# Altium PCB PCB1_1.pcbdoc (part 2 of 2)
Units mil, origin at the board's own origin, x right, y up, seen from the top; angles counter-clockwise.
Board outline 2585 x 2710 mil, 2 copper layers (Top Layer, Bottom Layer); 39 components, 30 nets, 170 pads, 81 vias.
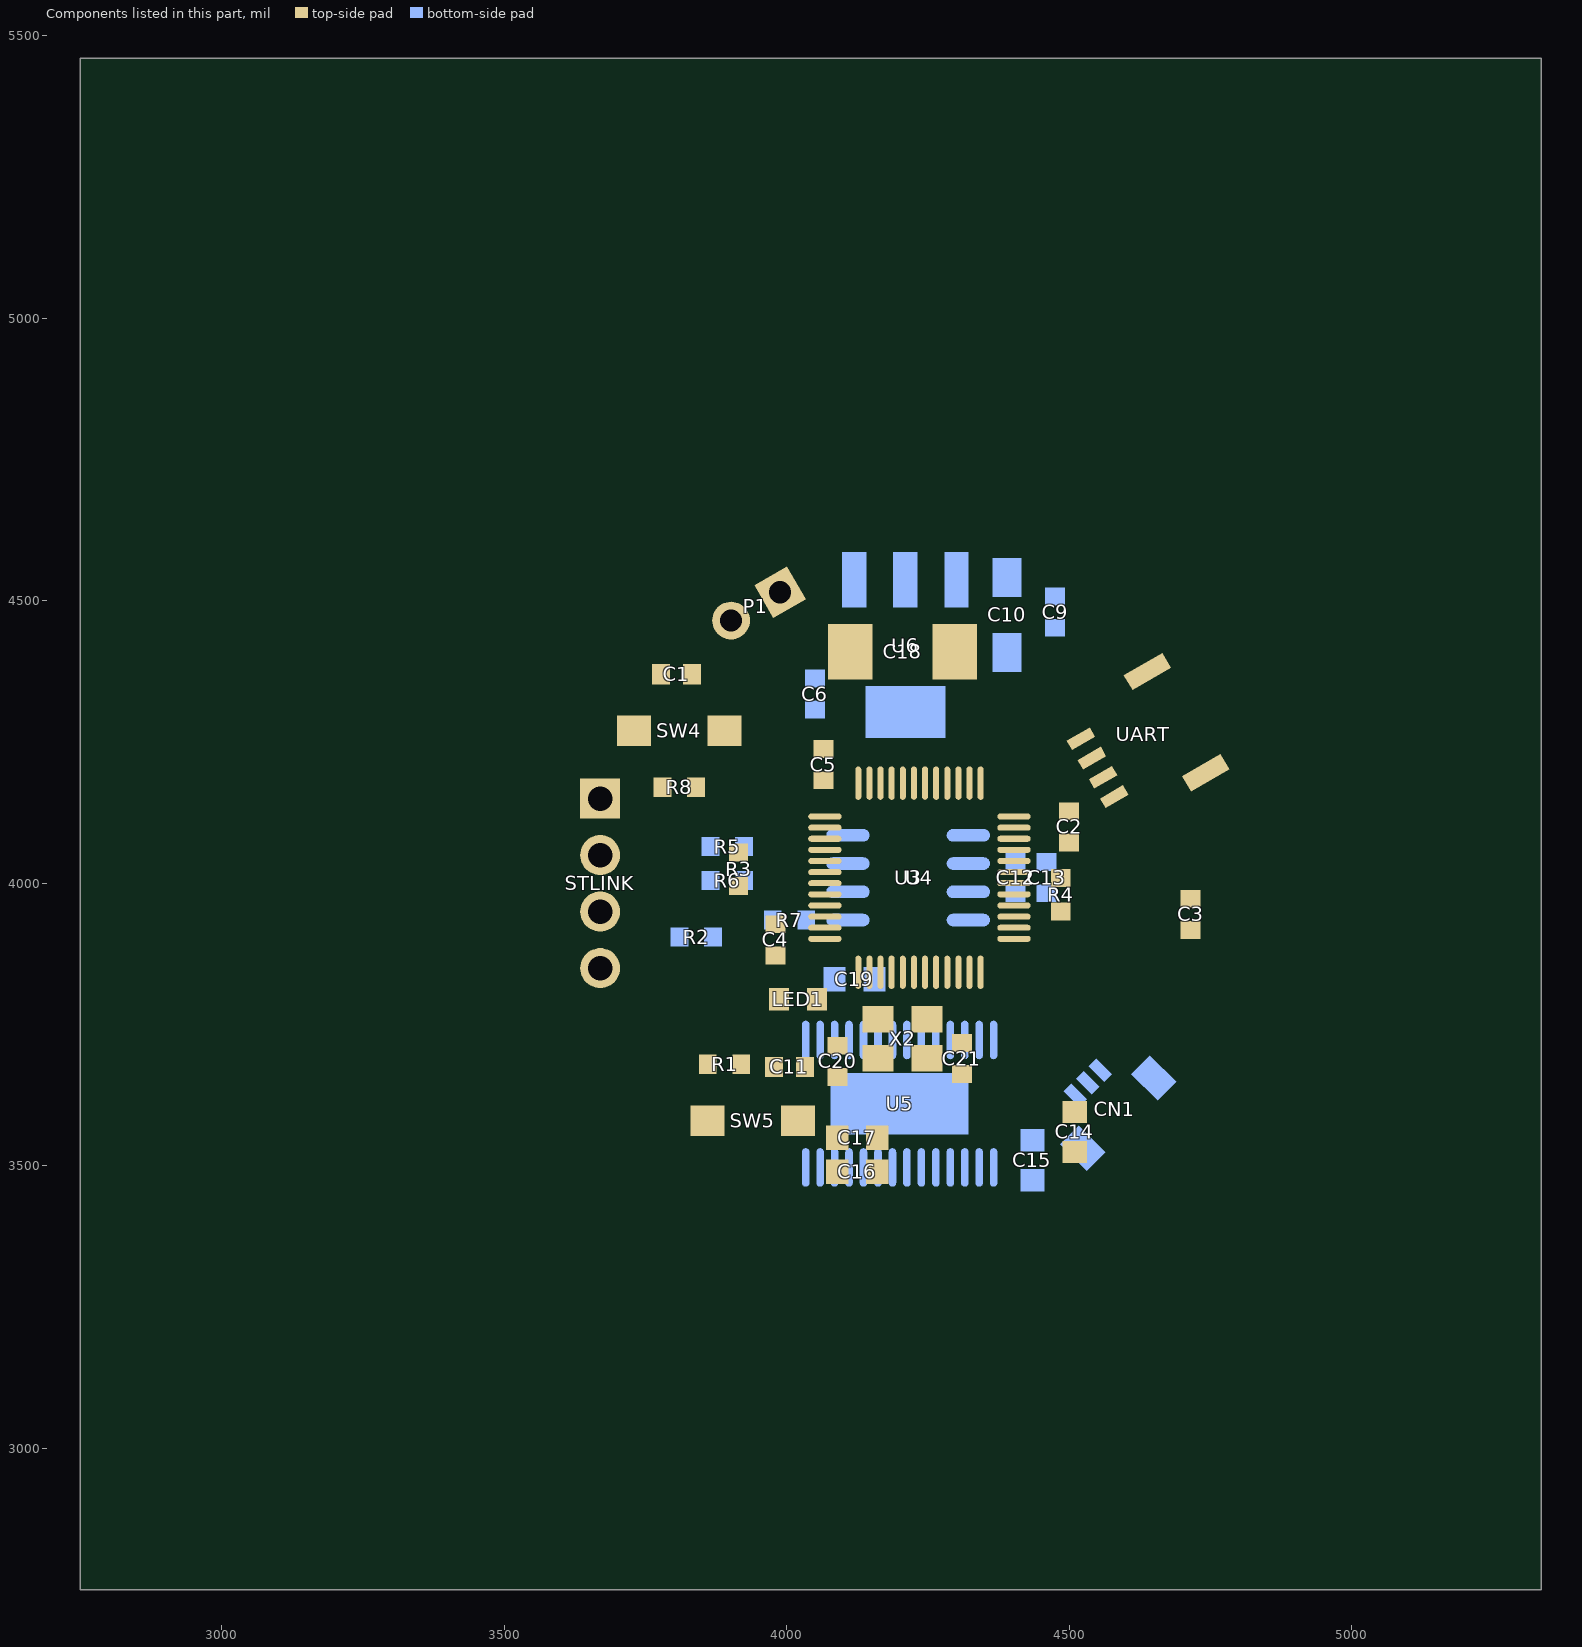
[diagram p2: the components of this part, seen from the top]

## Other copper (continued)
Bottom Layer:
  region net VCC3V3: 4535,4090 4555,4080 ccw(c4486.83,4080) 4552,4100 4538,4102.86 ccw(c4564.06,4090)
  region net $1N8596: 4074.57,3752.8 4074.51,3750.93 4074.32,3749.07 4074.01,3747.24 4073.57,3745.46 4073.02,3743.73 4072.34,3742.08 4071.55,3740.51 4070.64,3739.05 4069.6,3737.7 4069.05,3737.08 4068.46,3736.49 4067.84,3735.94 4067.2,3735.42 4066.52,3734.95 4065.82,3734.52 4065.09,3734.13 4064.33,3733.79 4063.55,3733.49 4062.73,3733.25 4061.89,3733.06 4061.02,3732.91 4060.12,3732.83 4059.2,3732.8 4059.2,3712.8 4074.57,3722.8 4094.57,3752.8
  region net VCC: 4284.6,3510.02 4294.6,3510.02 4289.6,3520.02 4282.53,3544.54
  region net EN: 4217.8,3699.27 4207.8,3699.21 ccw(c4229.16,3699.21) 4209.3,3691.34 4216.3,3690.77 ccw(c4192.97,3699.27)
  region net EN: 4278.14,3678.93 4277.29,3679.86 4276.44,3680.92 4275.6,3682.11 4274.39,3684.07 4273.24,3686.22 4272.18,3688.48 4271.24,3690.81 4270.43,3693.16 4269.79,3695.47 4269.32,3697.68 4269.12,3699.07 4269.01,3700.38 4269,3701 4259,3701 4258.95,3699.74 4258.79,3698.38 4258.55,3696.95 4258.02,3694.71 4257.31,3692.38 4256.46,3690.03 4255.47,3687.72 4254.39,3685.49 4253.21,3683.4 4251.98,3681.5 4251.14,3680.38 4250.29,3679.38 4249.86,3678.93 4256.93,3671.86 4257.63,3672.48 4258.41,3673.02 4259.24,3673.47 4260.13,3673.85 4261.06,3674.14 4262.03,3674.34 4263.01,3674.47 4264,3674.51 4264.99,3674.47 4265.97,3674.34 4266.94,3674.14 4267.87,3673.85 4268.76,3673.47 4269.59,3673.02 4270.37,3672.48 4271.07,3671.86
  region net RESET: 3893.54,3908.54 3886.46,3901.46 cw(c3873.59,3888.59) 3890.92,3894.18 3904.9,3900 cw(c3929.24,3944.24)
  region net VCC3V3: 3759.14,3915 3758.46,3915.02 3757.05,3915.16 3756.36,3915.29 3755.68,3915.45 3755.04,3915.64 3754.45,3915.87 3753.92,3916.12 3753.45,3916.4 3753.08,3916.72 3752.8,3917.06 3752.62,3917.42 3752.58,3917.82 3752.66,3918.24 3752.89,3918.68 3753.28,3919.14 3710.86,3876.72 3712.43,3878.19 3714.14,3879.62 3716.64,3881.45 3719.34,3883.21 3722.98,3885.26 3726.84,3887.16 3730.87,3888.89 3735.86,3890.71 3740.91,3892.25 3745.93,3893.46 3750.03,3894.22 3753.97,3894.73 3756.98,3894.95 3759.14,3895
  region net RESET: 4006.64,3875.78 4005.26,3874.51 4003.79,3873.36 4002.24,3872.32 4000.62,3871.42 3998.95,3870.65 3997.24,3870.02 3995.5,3869.55 3993.75,3869.23 3992,3869.08 3991.13,3869.07 3990.26,3869.1 3989.4,3869.18 3988.55,3869.31 3987.71,3869.48 3986.88,3869.7 3986.06,3869.97 3985.26,3870.28 3984.47,3870.65 3983.71,3871.07 3982.96,3871.54 3982.24,3872.07 3981.53,3872.65 3980.86,3873.28 3966.72,3859.14 3968.43,3857.34 3970.55,3854.85 3972.62,3852.13 3975.01,3848.62 3977.24,3844.88 3979.29,3840.99 3980.81,3837.67 3982.13,3834.31 3983.24,3830.95 3983.95,3828.29 3984.48,3825.67 3984.77,3823.74 3984.94,3821.84 3985,3820 4005,3820 4005.08,3822.5 4005.3,3825.13 4005.79,3828.56 4006.48,3832.11 4007.58,3836.45 4008.95,3840.8 4010.57,3845.08 4012.09,3848.54 4013.76,3851.83 4015.19,3854.32 4016.7,3856.66 4018.28,3858.81 4019.52,3860.29 4020.78,3861.64
  region net SDA: 3950,4015 3945.86,3995 ccw(c3945.86,4044.67) 3962.86,3998 3962.86,4012 ccw(c3950,3985.94)
  region net SCL: 3990,4025 3994.14,4045 ccw(c3994.14,3995.33) 3977.14,4042 3977.14,4028 ccw(c3990,4054.06)
  region net VCC: 4380.86,4513.11 4382.23,4514.39 4383.75,4515.67 4386.01,4517.36 4389.13,4519.42 4392.54,4521.4 4396.92,4523.63 4401.51,4525.68 4406.2,4527.48 4410.87,4528.99 4414.69,4530 4418.35,4530.76 4421.14,4531.16 4423.12,4531.33 4425,4531.39 4360.86,4531.39 4361.54,4531.37 4362.95,4531.23 4363.64,4531.1 4364.32,4530.94 4364.96,4530.75 4365.55,4530.52 4366.08,4530.27 4366.55,4529.99 4366.92,4529.67 4367.2,4529.33 4367.38,4528.97 4367.42,4528.57 4367.34,4528.15 4367.11,4527.71 4366.72,4527.25
  region net VCC3V3: 4306.72,4244.14 4308,4242.77 4309.28,4241.25 4310.97,4238.99 4313.03,4235.87 4315.01,4232.46 4317.24,4228.08 4319.29,4223.49 4321.09,4218.8 4322.6,4214.13 4323.61,4210.31 4324.37,4206.65 4324.77,4203.86 4324.94,4201.88 4325,4200 4345,4200 4335,4220 4320.86,4258.28
  region net VCC: 4115,3461.34 4105,3461.34 4104.98,3460.77 4104.91,3460.2 4104.8,3459.63 4104.66,3459.07 4104.48,3458.51 4104.02,3457.4 4103.46,3456.32 4102.81,3455.28 4102.11,3454.3 4101,3452.94 4119,3452.94 4117.89,3454.3 4117.19,3455.28 4116.54,3456.32 4115.98,3457.4 4115.52,3458.51 4115.34,3459.07 4115.2,3459.63 4115.09,3460.2 4115.02,3460.77
  region net V: 4206.98,3450.09 4199.91,3443.02 4200.3,3442.6 4200.65,3442.15 4200.98,3441.67 4201.27,3441.17 4201.54,3440.64 4202,3439.54 4202.37,3438.38 4202.65,3437.19 4202.85,3436 4203.02,3434.25 4215.75,3446.98 4214,3447.15 4212.81,3447.35 4211.62,3447.63 4210.46,3448 4209.36,3448.46 4208.83,3448.73 4208.33,3449.02 4207.85,3449.35 4207.4,3449.7
  region net W: 4171.98,3450.09 4164.91,3443.02 4165.3,3442.6 4165.65,3442.15 4165.98,3441.67 4166.27,3441.17 4166.54,3440.64 4167,3439.54 4167.37,3438.38 4167.65,3437.19 4167.85,3436 4168.02,3434.25 4180.75,3446.98 4179,3447.15 4177.81,3447.35 4176.62,3447.63 4175.46,3448 4174.36,3448.46 4173.83,3448.73 4173.33,3449.02 4172.85,3449.35 4172.4,3449.7
  region net $1N8586: 4369.84,3472.24 4362.76,3465.16 4363.08,3464.67 4363.24,3464 4363.29,3463.22 4363.26,3462.37 4363.03,3459.89 4363.02,3459.25 4375.75,3471.98 4375.11,3471.97 4372.63,3471.74 4371.78,3471.71 4371,3471.76 4370.33,3471.92
  region net $1N8587: 4345.7,3471.34 4335.7,3471.34 4335.77,3470.42 4336.39,3466.93 4336.54,3465.74 4336.56,3464.63 4336.4,3463.68 4336,3462.94 4354,3462.94 4353.56,3463.38 4352.46,3464.32 4349.07,3466.84 4347.78,3467.92 4347.21,3468.47 4346.71,3469.03 4346.29,3469.6 4345.97,3470.17 4345.77,3470.75
  region net $1N8589: 4323.02,3434.91 4330.09,3441.98 4329.7,3442.4 4329.35,3442.85 4329.02,3443.33 4328.73,3443.83 4328.46,3444.36 4328,3445.46 4327.63,3446.62 4327.35,3447.81 4327.15,3449 4326.98,3450.75 4314.25,3438.02 4316,3437.85 4317.19,3437.65 4318.38,3437.37 4319.54,3437 4320.64,3436.54 4321.17,3436.27 4321.67,3435.98 4322.15,3435.65 4322.6,3435.3
  region net $1N8589: 4320.2,3466.34 4310.2,3466.34 4310.18,3465.75 4310.11,3465.16 4309.99,3464.59 4309.84,3464.02 4309.65,3463.46 4309.42,3462.91 4308.89,3461.84 4308.25,3460.8 4307.54,3459.81 4306.39,3458.39 4306,3457.94 4324,3457.94 4323.29,3458.8 4322.6,3459.75 4321.96,3460.78 4321.39,3461.87 4320.9,3462.99 4320.53,3464.12 4320.39,3464.68 4320.29,3465.24 4320.22,3465.79
  region net U: 4269,3456.34 4259,3456.34 4259.04,3455.83 4259.16,3455.29 4259.34,3454.74 4259.82,3453.61 4260.92,3451.32 4261.14,3450.77 4261.32,3450.23 4261.43,3449.72 4261.47,3449.23 4261.42,3448.76 4261.27,3448.33 4261,3447.94 4279,3447.94 4278.48,3448.46 4277.85,3448.96 4276.38,3449.91 4273.06,3451.78 4271.5,3452.77 4270.82,3453.29 4270.21,3453.83 4269.71,3454.4 4269.33,3455.01 4269.08,3455.65
  region net EN: 4248.02,3934.91 4255.09,3941.98 4254.7,3942.4 4254.35,3942.85 4254.02,3943.33 4253.73,3943.83 4253.46,3944.36 4253,3945.46 4252.63,3946.62 4252.35,3947.81 4252.15,3949 4251.98,3950.75 4239.25,3938.02 4241,3937.85 4242.19,3937.65 4243.38,3937.37 4244.54,3937 4245.64,3936.54 4246.17,3936.27 4246.67,3935.98 4247.15,3935.65 4247.6,3935.3
  region net RESET: 3894.48,3907.59 3887.41,3900.52 3887.75,3900.09 3888.01,3899.57 3888.2,3898.97 3888.33,3898.31 3888.41,3897.58 3888.44,3896.02 3888.28,3893.53 3888.03,3890.47 3888.01,3889.82 3888.02,3889.25 3900.75,3901.98 3900.06,3902.05 3899.47,3902.17 3898.95,3902.35 3898.51,3902.57 3898.12,3902.83 3897.78,3903.13 3897.47,3903.46 3897.19,3903.83 3896.38,3905.1 3895.76,3906.06 3895.39,3906.56 3894.97,3907.07
  region net PWM1: 4357.41,3779.48 4364.48,3772.41 4364.97,3772.93 4365.39,3773.44 4366.08,3774.43 4366.92,3775.77 4367.19,3776.17 4367.47,3776.54 4367.78,3776.87 4368.12,3777.17 4368.51,3777.43 4368.95,3777.65 4369.47,3777.83 4370.06,3777.95 4370.75,3778.02 4358.02,3790.75 4358.01,3790.18 4358.07,3788.83 4358.41,3784.81 4358.44,3783.18 4358.41,3782.42 4358.33,3781.69 4358.2,3781.03 4358.01,3780.43 4357.75,3779.91
  region net PWM2: 4314.15,3786.22 4321.22,3779.15 4321.76,3779.57 4322.39,3779.86 4323.09,3780.01 4323.85,3780.06 4324.66,3780.02 4325.51,3779.9 4327.31,3779.5 4330.98,3778.47 4332.69,3778.11 4333.49,3778.02 4334.22,3778.02 4321.5,3790.75 4321.21,3789.87 4320.54,3789.18 4319.59,3788.64 4317.26,3787.78 4316.07,3787.35 4315,3786.84
  region net PWM3: 4278.66,3800 4278.66,3790 4279.23,3789.98 4279.8,3789.91 4280.37,3789.8 4280.93,3789.66 4281.49,3789.48 4282.6,3789.02 4283.68,3788.46 4284.72,3787.81 4285.7,3787.11 4287.06,3786 4287.06,3804 4285.7,3802.89 4284.72,3802.19 4283.68,3801.54 4282.6,3800.98 4281.49,3800.52 4280.93,3800.34 4280.37,3800.2 4279.8,3800.09 4279.23,3800.02
  region net $1N18711: 4080.54,3925 4080.54,3945 cw(c4080.54,4012.72) 4050.54,3952.01 4050.54,3917.99 cw(c4080.54,3857.28)
  region net $1N8589: 4402.74,3459.81 4402.74,3445.67 cw(c4425.24,3423.17) 4422.55,3454.88 4413.35,3481.02 cw(c4376.22,3486.33)
  region net VCC: 4398.35,3549.87 4398.35,3539.87 cw(c4398.35,3521.12) 4413.35,3532.37 4413.35,3557.37 cw(c4398.35,3568.62)
  region net VCC3V3: 4090,4297.44 4090,4317.44 cw(c4090,4436.2) 4067.72,4319.55 4067.72,4295.33 cw(c4090,4178.69)
  region net VCC3V3: 4011.07,4280.21 4029.62,4270.48 cw(c4085.93,4214.17) 4067.72,4291.69 4032.28,4322.64 cw(c3958.04,4333.25)
  region net $1N8596: 4059.2,3712.8 4059.2,3732.8 4057.44,3732.87 4055.7,3733.06 4053.99,3733.38 4052.32,3733.83 4050.7,3734.39 4049.15,3735.07 4047.68,3735.87 4046.31,3736.78 4045.05,3737.81 4044.46,3738.36 4043.91,3738.93 4043.39,3739.54 4042.91,3740.17 4042.47,3740.82 4042.06,3741.5 4041.7,3742.21 4041.38,3742.93 4041.1,3743.69 4040.87,3744.46 4040.69,3745.26 4040.56,3746.09 4040.48,3746.93 4040.45,3747.8 4040.45,3697.8 4040.48,3698.67 4040.56,3699.51 4040.69,3700.34 4040.87,3701.14 4041.1,3701.91 4041.38,3702.67 4041.7,3703.39 4042.06,3704.1 4042.47,3704.78 4042.91,3705.43 4043.39,3706.06 4043.91,3706.67 4044.46,3707.24 4045.05,3707.79 4046.31,3708.82 4047.68,3709.73 4049.15,3710.53 4050.7,3711.21 4052.32,3711.77 4053.99,3712.22 4055.7,3712.54 4057.44,3712.73
  region net $1N8596: 4084.8,3712.8 4084.8,3732.8 4083.04,3732.86 4081.28,3733.06 4079.56,3733.38 4077.88,3733.82 4076.25,3734.38 4074.69,3735.06 4073.22,3735.86 4071.84,3736.77 4070.57,3737.78 4069.98,3738.34 4069.43,3738.91 4068.91,3739.52 4068.42,3740.14 4067.98,3740.8 4067.57,3741.48 4067.2,3742.19 4066.88,3742.92 4066.6,3743.67 4066.37,3744.45 4066.19,3745.25 4066.06,3746.08 4065.98,3746.93 4065.95,3747.8 4065.95,3697.8 4065.98,3698.67 4066.06,3699.52 4066.19,3700.35 4066.37,3701.15 4066.6,3701.93 4066.88,3702.68 4067.2,3703.41 4067.57,3704.12 4067.98,3704.8 4068.42,3705.46 4068.91,3706.08 4069.43,3706.69 4069.98,3707.26 4070.57,3707.82 4071.84,3708.83 4073.22,3709.74 4074.69,3710.54 4076.25,3711.22 4077.88,3711.78 4079.56,3712.22 4081.28,3712.54 4083.04,3712.74
  region net $1N8596: 4033.7,3732.8 4033.7,3712.8 4035.46,3712.73 4037.2,3712.54 4038.91,3712.22 4040.58,3711.77 4042.2,3711.21 4043.75,3710.53 4045.22,3709.73 4046.59,3708.82 4047.85,3707.79 4048.44,3707.24 4048.99,3706.67 4049.51,3706.06 4049.99,3705.43 4050.43,3704.78 4050.84,3704.1 4051.2,3703.39 4051.52,3702.67 4051.8,3701.91 4052.03,3701.14 4052.21,3700.34 4052.34,3699.51 4052.42,3698.67 4052.45,3697.8 4052.45,3747.8 4052.42,3746.93 4052.34,3746.09 4052.21,3745.26 4052.03,3744.46 4051.8,3743.69 4051.52,3742.93 4051.2,3742.21 4050.84,3741.5 4050.43,3740.82 4049.99,3740.17 4049.51,3739.54 4048.99,3738.93 4048.44,3738.36 4047.85,3737.81 4046.59,3736.78 4045.22,3735.87 4043.75,3735.07 4042.2,3734.39 4040.58,3733.83 4038.91,3733.38 4037.2,3733.06 4035.46,3732.87
  region net $1N8596: 4059.2,3732.8 4059.2,3712.8 4060.96,3712.74 4062.72,3712.54 4064.44,3712.22 4066.12,3711.78 4067.75,3711.22 4069.31,3710.54 4070.78,3709.74 4072.16,3708.83 4073.43,3707.82 4074.02,3707.26 4074.57,3706.69 4075.09,3706.08 4075.58,3705.46 4076.02,3704.8 4076.43,3704.12 4076.8,3703.41 4077.12,3702.68 4077.4,3701.93 4077.63,3701.15 4077.81,3700.35 4077.94,3699.52 4078.02,3698.67 4078.05,3697.8 4078.05,3747.8 4078.02,3746.93 4077.94,3746.08 4077.81,3745.25 4077.63,3744.45 4077.4,3743.67 4077.12,3742.92 4076.8,3742.19 4076.43,3741.48 4076.02,3740.8 4075.58,3740.14 4075.09,3739.52 4074.57,3738.91 4074.02,3738.34 4073.43,3737.78 4072.16,3736.77 4070.78,3735.86 4069.31,3735.06 4067.75,3734.38 4066.12,3733.82 4064.44,3733.38 4062.72,3733.06 4060.96,3732.86
  region net EN: 4217.8,3769.68 4207.8,3769.68 4207.85,3767.77 4208.08,3764.97 4208.44,3761.59 4208.5,3760.22 4208.48,3759.31 4208.4,3758.39 4208.25,3757.43 4208.03,3756.44 4207.71,3755.41 4207.28,3754.31 4206.75,3753.13 4218.85,3753.13 4218.32,3754.31 4217.89,3755.41 4217.57,3756.44 4217.35,3757.43 4217.2,3758.39 4217.12,3759.31 4217.1,3760.22 4217.16,3761.59 4217.62,3766.04 4217.78,3768.38
  region net EN: 4207.8,3687.8 4217.8,3687.8 4217.88,3688.37 4219.28,3693.97 4219.47,3694.88 4219.55,3695.45 4206.05,3695.45 4206.32,3694.82 4207.53,3689.56
  region net PWM3: 4245,3766.57 4235,3770.98 4234.86,3769.84 4231.69,3750.54 4231.65,3750.15 4245.15,3750.15
  region net EN: 4259,3686 4269,3686 4269.03,3687.65 4269.17,3689.32 4269.3,3690.14 4269.49,3690.94 4269.73,3691.72 4270.05,3692.47 4257.95,3692.47 4258.27,3691.72 4258.51,3690.94 4258.7,3690.14 4258.83,3689.32 4258.97,3687.65
  region net VCC: 4105,3450.8 4115,3449.91 4116.47,3463.37 4117.15,3469.85 4103.65,3469.85 4104.57,3457.53
  region net W: 4156.6,3453.4 4166.6,3453.4 4168.27,3468.9 4168.35,3469.85 4154.85,3469.85 4156.52,3454.35
  region net V: 4182.2,3462.8 4192.2,3462.8 4192.28,3463.35 4193.4,3467.44 4193.87,3469.3 4193.95,3469.85 4180.45,3469.85 4180.72,3469.31 4181.93,3464.46
  region net U: 4259,3450.32 4269,3450.32 4270.67,3468.76 4270.75,3469.85 4257.25,3469.85 4258.92,3451.4
  region net VCC: 4306.96,3534.89 4299.82,3541.9 4298.63,3540.78 4297.44,3539.79 4296.27,3538.93 4294.72,3537.94 4292.85,3536.9 4289.08,3535.03 4287.86,3534.37 4287.01,3533.85 4286.48,3533.47 4285.98,3533.08 4285.51,3532.65 4285.08,3532.18 4284.68,3531.68 4284.31,3531.13 4283.98,3530.53 4283.69,3529.88 4283.44,3529.17 4283.23,3528.39 4283.07,3527.55 4282.95,3526.63 4282.87,3525.63 4282.85,3524.55 4296.35,3524.55 4296.44,3525.25 4296.7,3525.96 4297.1,3526.67 4297.63,3527.37 4298.28,3528.07 4299.01,3528.77 4300.66,3530.13 4304.99,3533.27 4306.4,3534.37
  region net $1N8589: 4310.2,3450.32 4320.2,3450.32 4321.87,3468.76 4321.95,3469.85 4308.45,3469.85 4308.72,3467.36
  region net $1N8587: 4335.7,3459.3 4345.7,3459.3 4345.78,3460 4347.37,3469.15 4347.45,3469.85 4333.95,3469.85 4334.03,3469.72 4335.15,3463.34 4335.62,3460.08
  region net $1N8586: 4371.46,3456.46 4378.54,3463.54 4378.02,3464.02 4377.51,3464.44 4376.52,3465.13 4375.17,3465.99 4374.76,3466.27 4374.4,3466.56 4374.06,3466.87 4373.77,3467.22 4373.52,3467.61 4373.32,3468.06 4373.17,3468.58 4373.08,3469.17 4373.05,3469.85 4359.55,3469.85 4359.94,3470.61 4360.99,3469.95 4362.53,3468.25 4368.35,3460.4 4370.1,3458.07
  region net VCC3V3: 3855.34,4017.99 3875.34,4017.99 cw(c4089.73,4017.99) 3877.45,4047.99 3853.23,4047.99 cw(c3640.95,4017.99)
  region net $1N8596: 4074.57,3778.35 4094.57,3778.35 cw(c4308.96,3778.35) 4096.68,3808.35 4072.46,3808.35 cw(c3860.18,3778.35)
  region net $1N18711: 4046.28,3945 4046.28,3925 4046.96,3925.03 4047.68,3925.11 4049.24,3925.42 4050.92,3925.89 4055.5,3927.52 4062.14,3929.94 4063.94,3930.45 4065.64,3930.83 4066.45,3930.94 4067.22,3931.01 4067.96,3931.02 4068.65,3930.98 4069.3,3930.86 4069.91,3930.68 4070.46,3930.42 4070.95,3930.08 4071.39,3929.65 4071.77,3929.14 4071.77,3940.86 4071.39,3940.35 4070.95,3939.92 4070.46,3939.58 4069.91,3939.32 4069.3,3939.14 4068.65,3939.02 4067.96,3938.98 4067.22,3938.99 4066.45,3939.06 4064.8,3939.34 4063.05,3939.79 4060.28,3940.69 4052.7,3943.51 4050.06,3944.36 4048.44,3944.76 4047.68,3944.89 4046.96,3944.97
  region net SDA: 4046.28,3995 4046.28,3975 4081.3,3973.81 4081.3,3996.19
  region net SCL: 4046.28,4045 4046.28,4025 4081.3,4023.81 4081.3,4046.19
  region net VCC3V3: 4383.72,4025 4383.72,4045 4348.7,4046.19 4348.7,4023.81
  region net VCC3V3: 4331.5,4076.19 4311.5,4076.19 4311.34,4066.5 4311.04,4062.58 4310.71,4060.11 4310.37,4058.33 4309.95,4056.64 4309.44,4055.04 4309.05,4054.03 4308.6,4053.07 4308.11,4052.16 4307.56,4051.3 4306.95,4050.5 4306.29,4049.76 4305.56,4049.08 4304.77,4048.47 4303.91,4047.92 4302.98,4047.44 4301.98,4047.04 4300.9,4046.71 4299.75,4046.46 4298.51,4046.29 4297.19,4046.2 4296.5,4046.19 4346.5,4046.19 4345.14,4046.23 4343.86,4046.36 4342.66,4046.57 4341.55,4046.86 4340.51,4047.23 4339.55,4047.67 4338.65,4048.19 4337.83,4048.77 4337.07,4049.41 4336.37,4050.13 4335.74,4050.9 4335.16,4051.73 4334.64,4052.61 4334.17,4053.55 4333.75,4054.53 4333.38,4055.56 4332.9,4057.19 4332.51,4058.91 4332.11,4061.33 4331.78,4064.52 4331.54,4069.9
  region net VCC3V3: 4311.5,4043.81 4331.5,4043.81 4331.66,4053.5 4331.96,4057.42 4332.29,4059.89 4332.63,4061.67 4333.05,4063.36 4333.56,4064.96 4333.95,4065.97 4334.4,4066.93 4334.89,4067.84 4335.44,4068.7 4336.05,4069.5 4336.71,4070.24 4337.44,4070.92 4338.23,4071.53 4339.09,4072.08 4340.02,4072.56 4341.02,4072.96 4342.1,4073.29 4343.25,4073.54 4344.49,4073.71 4345.81,4073.8 4346.5,4073.81 4296.5,4073.81 4297.86,4073.77 4299.14,4073.64 4300.34,4073.43 4301.45,4073.14 4302.49,4072.77 4303.45,4072.33 4304.35,4071.81 4305.17,4071.23 4305.93,4070.59 4306.63,4069.87 4307.26,4069.1 4307.84,4068.27 4308.36,4067.39 4308.83,4066.45 4309.25,4065.47 4309.62,4064.44 4310.1,4062.81 4310.49,4061.09 4310.89,4058.67 4311.22,4055.48 4311.46,4050.1
  region net VCC3V3: 3711.18,3877.04 3697.04,3891.18 3695.8,3890.02 3694.57,3889.01 3693.75,3888.42 3692.94,3887.89 3692.12,3887.42 3691.31,3887.01 3690.49,3886.65 3689.67,3886.33 3688.43,3885.95 3687.19,3885.65 3685.92,3885.44 3684.64,3885.3 3682.9,3885.21 3679.74,3885.23 3671.73,3885.48 3668.36,3885.4 3667.78,3885.36 3705.36,3847.78 3705.48,3851.18 3705.26,3858.8 3705.2,3862.46 3705.27,3864.21 3705.39,3865.5 3705.58,3866.77 3705.84,3868.02 3706.19,3869.26 3706.48,3870.08 3706.82,3870.9 3707.21,3871.71 3707.65,3872.53 3708.15,3873.34 3708.71,3874.16 3709.66,3875.39 3710.78,3876.62
  region net SWCLK: 3711.18,4077.04 3697.04,4091.18 3695.8,4090.02 3694.57,4089.01 3693.75,4088.42 3692.94,4087.89 3692.12,4087.42 3691.31,4087.01 3690.49,4086.65 3689.67,4086.33 3688.43,4085.95 3687.19,4085.65 3685.92,4085.44 3684.64,4085.3 3682.9,4085.21 3679.74,4085.23 3671.73,4085.48 3668.36,4085.4 3667.78,4085.36 3705.36,4047.78 3705.48,4051.18 3705.26,4058.8 3705.2,4062.46 3705.27,4064.21 3705.39,4065.5 3705.58,4066.77 3705.84,4068.02 3706.19,4069.26 3706.48,4070.08 3706.82,4070.9 3707.21,4071.71 3707.65,4072.53 3708.15,4073.34 3708.71,4074.16 3709.66,4075.39 3710.78,4076.62
  region net SWDIO: 3726.65,4192.5 3712.5,4206.65 cw(c3659.47,4259.68) 3670.08,4185.43 3705.43,4150.08 cw(c3779.68,4139.47)
  region net SDA: 3970,3995 3970,4015 cw(c3970,4080.44) 3940.54,4022.01 3940.54,3987.99 cw(c3970,3929.56)
  region net VCC3V3: 3875.34,4052.01 3855.34,4052.01 cw(c3775.81,4052.01) 3849.46,4022.01 3881.22,4022.01 cw(c3954.87,4052.01)
  region net VCC3V3: 3825,4015 3825,3995 cw(c3825,3852.08) 3849.46,3992.89 3849.46,4017.11 cw(c3825,4157.92)
  region net VCC3V3: 3764.46,3915 3764.46,3895 cw(c3764.46,3827.28) 3794.46,3887.99 3794.46,3922.01 cw(c3764.46,3982.72)
  region net VCC3V3: 4220,4379.14 4200,4379.14 cw(c4162.5,4379.14) 4185,4349.14 4235,4349.14 cw(c4257.5,4379.14)
  region net VCC3V3: 4109.13,4317.44 4109.13,4297.44 cw(c4109.13,4259.94) 4139.13,4282.44 4139.13,4332.44 cw(c4109.13,4354.94)
  region net VCC3V3: 4302.08,4248.78 4302.08,4277.06 cw(c4355.11,4330.1) 4280.87,4319.49 4272.64,4257.01 cw(c4280.05,4226.75)
  region net VCC: 4352.2,4531.39 4352.2,4551.39 cw(c4352.2,4588.89) 4322.2,4566.39 4322.2,4516.39 cw(c4352.2,4493.89)
  region net VCC3V3: 4200,4457.71 4220,4457.71 cw(c4264.44,4457.71) 4231.65,4487.71 4188.35,4487.71 cw(c4155.56,4457.71)
  region net VCC3V3: 4357.28,4045 4357.28,4025 cw(c4357.28,3810.61) 4387.28,4022.89 4387.28,4047.11 cw(c4357.28,4259.39)
  region net VCC3V3: 4452.72,4025 4452.72,4045 cw(c4452.72,4103.32) 4422.72,4053.31 4422.72,4021.81 cw(c4452.72,3882.25)
  region net VCC3V3: 4357.28,4045 4357.28,4025 cw(c4357.28,3810.61) 4387.28,4022.89 4387.28,4047.11 cw(c4357.28,4259.39)
  region net VCC3V3: 4452.72,4025 4452.72,4045 cw(c4452.72,4103.32) 4422.72,4053.31 4422.72,4021.81 cw(c4452.72,3882.25)
  region net VCC3V3: 4502.56,4027.56 4502.56,4047.56 cw(c4502.56,4104.12) 4477.72,4053.31 4477.72,4021.81 cw(c4502.56,3971)
  region net VCC3V3: 4412.28,4045 4412.28,4025 cw(c4412.28,3810.61) 4442.28,4022.89 4442.28,4047.11 cw(c4412.28,4259.39)
  region net VCC: 4436.17,4531.39 4436.17,4551.39 cw(c4436.17,4573.12) 4415.51,4566.39 4415.51,4516.39 cw(c4436.17,4509.66)
  region net VCC: 4334.49,4551.39 4334.49,4531.39 cw(c4334.49,4493.89) 4364.49,4516.39 4364.49,4566.39 cw(c4334.49,4588.89)
  region net VCC: 4447.18,4544.52 4436.07,4527.35 cw(c4376.28,4467.55) 4457.28,4491.81 4489.61,4523.31 cw(c4500.21,4597.55)

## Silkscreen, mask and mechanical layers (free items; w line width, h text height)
Mechanical Layer:
  circle w1 net "": c3960,4370 r44
  circle w1 net "": c4470,4370 r44
  lines w1 net "": 3722.64,3795 ccw(c3830,3795) 3738.24,3739.25 ccw(c3742.52,3741.85) 3742.52,3736.85 3917.48,3736.85 ccw(c3917.48,3741.85) 3921.76,3739.25 ccw(c3830,3795) 3937.36,3795 ccw(c3830,3795) 3921.76,3850.75 ccw(c3917.48,3848.15) 3917.48,3853.15 3742.52,3853.15 ccw(c3742.52,3848.15) 3738.24,3850.75 ccw(c3830,3795) 3722.64,3795 ; 4494.65,3795 ccw(c4602.02,3795) 4510.26,3739.25 ccw(c4514.53,3741.85) 4514.53,3736.85 4689.5,3736.85 ccw(c4689.5,3741.85) 4693.77,3739.25 ccw(c4602.02,3795) 4709.38,3795 ccw(c4602.02,3795) 4693.77,3850.75 ccw(c4689.5,3848.15) 4689.5,3853.15 4514.53,3853.15 ccw(c4514.53,3848.15) 4510.26,3850.75 ccw(c4602.02,3795) 4494.65,3795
